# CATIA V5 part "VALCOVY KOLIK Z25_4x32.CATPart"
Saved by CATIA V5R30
Part number: VALCOVY KOLIK Z25/4x32
Bounding box of the stored display mesh (mm): x -32 to -0.009, y -2 to 2, z -2 to 2
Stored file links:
  C:\Users\ondra\Desktop\PŘÍLOHA P III\CATIA\VALCOVY KOLIK Z25_4x32.CATPart
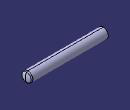
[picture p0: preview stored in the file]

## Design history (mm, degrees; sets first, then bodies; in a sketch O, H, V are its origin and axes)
Set1
  DatumSurface1 to DatumSurface8 "Z25/4x32"
  Join1: Elements (DatumSurface1; DatumSurface2; DatumSurface3; DatumSurface4; DatumSurface5; DatumSurface6; DatumSurface7; DatumSurface8)
Body1 (main body)
  CloseSurface1: CloseElement Join1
